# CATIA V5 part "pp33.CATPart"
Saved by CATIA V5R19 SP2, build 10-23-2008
Part number: pp33
Publications: "Line.1", "Point.2", "Plane.1", "Line.2"
Bounding box of the stored display mesh (mm): x -20 to 0, y -420 to 0, z -50 to 50
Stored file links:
  C:\Users\Welcome\Documents\thinkm2\pp33.CATPart
  C:\Users\Welcome\Documents\thinkm2\Brasmeca.CATProduct
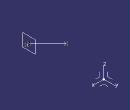
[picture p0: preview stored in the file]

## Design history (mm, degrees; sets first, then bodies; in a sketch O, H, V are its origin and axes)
AxisSystem1: origin (0, 0, 0), X (1, 0, 0), Y (0, 1, 0), Z (0, 0, 1)
Set1
  Point1: linked copy from another document
  Point2: linked copy from another document
Body1 (main body)
  Line1: type PtDir, RefPoint Point1, Direction edge [XY plane of AxisSystem1 | ZX plane of AxisSystem1], Start 0, End -20
  Point3: type OnCurve, Support Line1, Length 5
  Plane1: type Normal, Curve Line1, RefPoint Point3
  Line2: type PtPt, FirstPoint Point3, SecondPoint Point2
